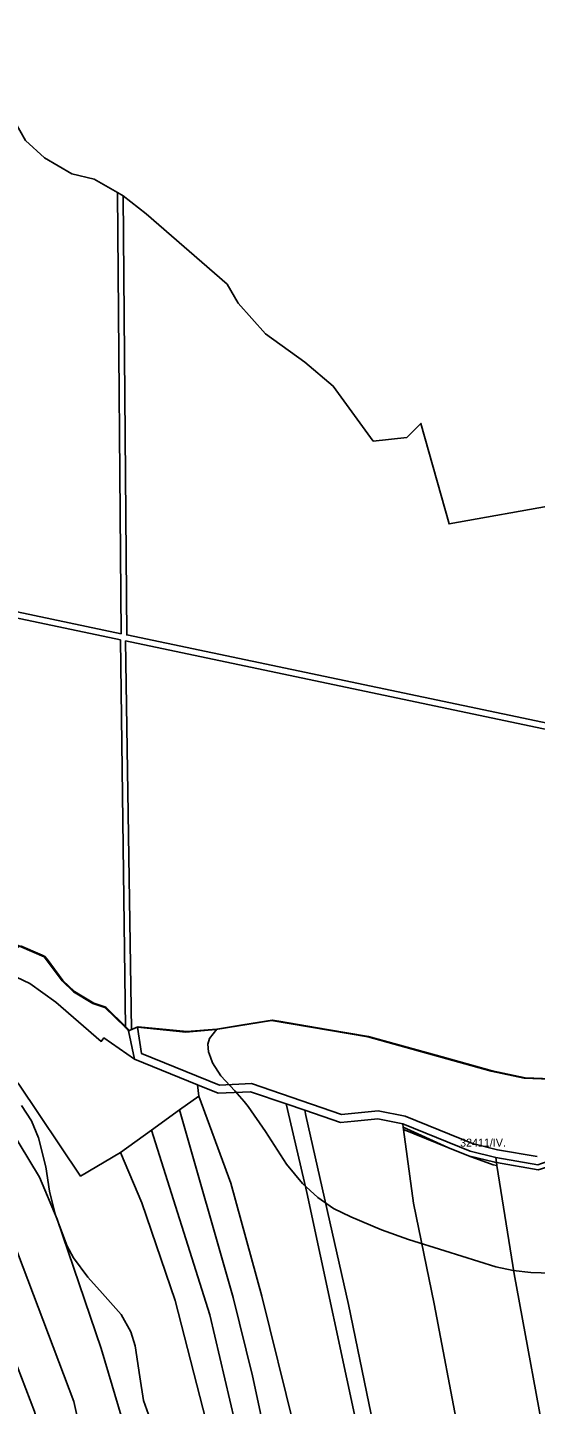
# Model space of a CAD drawing. Extents: x -535894 to -532834, y -1165802 to -1163645.
# Drawn here: x -534487 to -534170, y -1164507 to -1163647 of the extents above; entities that cross this region are included whole.
import ezdxf

# ---------------------------------------------------------------- set-up
doc = ezdxf.new("R2010")
doc.units = 0
for name, color, linetype in [('95560013', 7, 'Continuous'), ('95610013', 7, 'Continuous'), ('95620013', 7, 'Continuous'), ('95630013', 7, 'Continuous'), ('95640013', 7, 'Continuous'), ('95660013', 7, 'Continuous')]:
    doc.layers.add(name, color=color, linetype=linetype)

msp = doc.modelspace()

# ---------------------------------------------------------------- linework, layer by layer
at = {"layer": '95560013'}
for points in [[(-534485.85, -1164244.28), (-534469.68, -1164256.06), (-534441.39, -1164280.53), (-534439.7, -1164278.38), (-534420.68, -1164291.71), (-534381.33, -1164307.72), (-534380.51, -1164314.71), (-534392.48, -1164323.34), (-534409.97, -1164335.95), (-534429.42, -1164349.98), (-534454.21, -1164364.71), (-534492.77, -1164307.32), (-534515.72, -1164281.44), (-534526.13, -1164274.97), (-534521.16, -1164256.66), (-534507.27, -1164234.42)], [(-534526.13, -1164274.97), (-534515.72, -1164281.44), (-534492.77, -1164307.32), (-534454.21, -1164364.71), (-534429.42, -1164349.98), (-534416.02, -1164381.41), (-534395.29, -1164442.42), (-534374.06, -1164525.31), (-534335.46, -1164704.47), (-534321.03, -1164764.37), (-534369.38, -1164771.26), (-534395.1, -1164665.47), (-534403.85, -1164623.02), (-534425.95, -1164524.31), (-534441.36, -1164472.55), (-534468.86, -1164391.61), (-534480, -1164365.41), (-534516.93, -1164304.39), (-534530.72, -1164286.68)], [(-534532.67, -1164291.64), (-534530.72, -1164286.68), (-534516.93, -1164304.39), (-534480, -1164365.41), (-534468.86, -1164391.61), (-534441.36, -1164472.55), (-534425.95, -1164524.31), (-534403.85, -1164623.02), (-534395.1, -1164665.47), (-534369.38, -1164771.26), (-534394.4, -1164775.14), (-534435.14, -1164602.44), (-534447.18, -1164556.51), (-534458.51, -1164505.61), (-534503.01, -1164387.73), (-534528.59, -1164340.68), (-534546.29, -1164312.84), (-534540.94, -1164306.3)], [(-534368.45, -1164312.96), (-534348.23, -1164312.01), (-534325.91, -1164319.65), (-534325.1, -1164323.12), (-534312.95, -1164375.07), (-534279.41, -1164531.26), (-534235.38, -1164737.53), (-534263.41, -1164744.88), (-534259.95, -1164758.7), (-534270.37, -1164759.39), (-534289.39, -1164676.29), (-534296.14, -1164651.27), (-534310.82, -1164581.32), (-534320.94, -1164521.53), (-534341.14, -1164439.8), (-534360.37, -1164369.24), (-534380.51, -1164314.71), (-534381.33, -1164307.72)], [(-534552.41, -1164320.35), (-534546.29, -1164312.84), (-534528.59, -1164340.68), (-534503.01, -1164387.73), (-534458.51, -1164505.61), (-534447.18, -1164556.51), (-534435.14, -1164602.44), (-534394.4, -1164775.14), (-534417.97, -1164782.81), (-534422.37, -1164761.45), (-534445.23, -1164674.2), (-534452.73, -1164639.92), (-534475.43, -1164538.49), (-534482.99, -1164511.95), (-534496.61, -1164476.36), (-534524.39, -1164413.79), (-534547.27, -1164366.74), (-534567.13, -1164333.28)], [(-534380.51, -1164314.71), (-534360.37, -1164369.24), (-534341.14, -1164439.8), (-534320.94, -1164521.53), (-534310.82, -1164581.32), (-534296.14, -1164651.27), (-534289.39, -1164676.29), (-534270.37, -1164759.39), (-534285.75, -1164760.67), (-534304.35, -1164689.65), (-534328.76, -1164574.02), (-534346.86, -1164489.52), (-534358.97, -1164440.63), (-534392.48, -1164323.34)], [(-534392.48, -1164323.34), (-534358.97, -1164440.63), (-534346.86, -1164489.52), (-534328.76, -1164574.02), (-534304.35, -1164689.65), (-534285.75, -1164760.67), (-534302.74, -1164761.94), (-534316.61, -1164710.6), (-534338.42, -1164610.08), (-534358.04, -1164518.08), (-534373.64, -1164451.39), (-534409.97, -1164335.95)], [(-534325.91, -1164319.65), (-534314.28, -1164323.62), (-534313.54, -1164326.89), (-534286.98, -1164445.09), (-534267.22, -1164541.07), (-534255.41, -1164592.77), (-534227.83, -1164735.54), (-534235.38, -1164737.53), (-534279.41, -1164531.26), (-534312.95, -1164375.07), (-534325.1, -1164323.12)], [(-534314.28, -1164323.62), (-534291.92, -1164331.27), (-534283.19, -1164330.42), (-534268.67, -1164329.01), (-534253.1, -1164332.11), (-534252.81, -1164334.22), (-534252.63, -1164335.54), (-534246.42, -1164381.6), (-534233.53, -1164444.63), (-534218.39, -1164524.52), (-534206.45, -1164583.63), (-534189.15, -1164673.8), (-534171.37, -1164752.69), (-534179.77, -1164756.72), (-534195.92, -1164761.38), (-534216.66, -1164764.58), (-534218.72, -1164756.66), (-534224.44, -1164734.65), (-534227.83, -1164735.54), (-534255.41, -1164592.77), (-534267.22, -1164541.07), (-534286.98, -1164445.09), (-534313.54, -1164326.89)], [(-534578.03, -1164342.06), (-534567.13, -1164333.28), (-534547.27, -1164366.74), (-534524.39, -1164413.79), (-534496.61, -1164476.36), (-534482.99, -1164511.95), (-534475.43, -1164538.49), (-534452.73, -1164639.92), (-534445.23, -1164674.2), (-534422.37, -1164761.45), (-534417.97, -1164782.81), (-534464.01, -1164796.91), (-534483.14, -1164727.26), (-534507.98, -1164622.35), (-534527.6, -1164554.86), (-534532.98, -1164540.25), (-534563.85, -1164466.68), (-534596.51, -1164398.57), (-534611.82, -1164369.29), (-534589.62, -1164351.4)], [(-534409.97, -1164335.95), (-534373.64, -1164451.39), (-534358.04, -1164518.08), (-534338.42, -1164610.08), (-534316.61, -1164710.6), (-534302.74, -1164761.94), (-534321.03, -1164764.37), (-534335.46, -1164704.47), (-534374.06, -1164525.31), (-534395.29, -1164442.42), (-534416.02, -1164381.41), (-534429.42, -1164349.98)], [(-534252.63, -1164335.54), (-534225.01, -1164346.8), (-534212.04, -1164352.1), (-534196.56, -1164357.78), (-534194.29, -1164358.08), (-534183.63, -1164425.89), (-534161.35, -1164546.99), (-534154.51, -1164595.51), (-534134.42, -1164692.7), (-534129.11, -1164725.09), (-534140.42, -1164734.83), (-534159.42, -1164746.94), (-534171.37, -1164752.69), (-534189.15, -1164673.8), (-534206.45, -1164583.63), (-534218.39, -1164524.52), (-534233.53, -1164444.63), (-534246.42, -1164381.6)], [(-534212.04, -1164352.1), (-534195.66, -1164356.15), (-534194.56, -1164356.33), (-534194.29, -1164358.08), (-534196.56, -1164357.78)], [(-534143.2, -1164352.52), (-534139.1, -1164352.62), (-534137.95, -1164353.25), (-534137.54, -1164357.79), (-534134.7, -1164388.64), (-534128.98, -1164436.89), (-534104.44, -1164574.12), (-534091.65, -1164672.4), (-534102.21, -1164694.14), (-534107.73, -1164701.96), (-534116.22, -1164713.99), (-534129.11, -1164725.09), (-534134.42, -1164692.7), (-534154.51, -1164595.51), (-534161.35, -1164546.99), (-534183.63, -1164425.89), (-534194.29, -1164358.08), (-534194.56, -1164356.33), (-534168.47, -1164360.79), (-534166.4, -1164360.11)]]:
    msp.add_lwpolyline(points, close=True, dxfattribs=at)
msp.add_lwpolyline([(-534169.08, -1164352.57), (-534194.02, -1164348.32), (-534209.55, -1164344.47), (-534251.65, -1164327.3), (-534268.42, -1164323.97), (-534291.32, -1164326.19), (-534347.51, -1164306.97), (-534367.58, -1164307.92), (-534416.31, -1164288.09), (-534418.8, -1164271.7), (-534388.51, -1164274.7), (-534369.81, -1164273.2), (-534335.13, -1164267.45), (-534274.99, -1164277.69), (-534197.87, -1164299.21), (-534177.29, -1164303.6), (-534144.82, -1164304.74)], dxfattribs=at)
at = {"layer": '95610013'}
msp.add_lwpolyline([(-534492.39, -1164221.02), (-534477.05, -1164227.75), (-534465.85, -1164242.8), (-534458.72, -1164249.64), (-534446.52, -1164256.91), (-534439.05, -1164259.47), (-534426.3, -1164271.96), (-534424.3, -1164273.92), (-534420.68, -1164291.71), (-534439.7, -1164278.38), (-534441.39, -1164280.53), (-534469.68, -1164256.06), (-534485.85, -1164244.28), (-534507.27, -1164234.42), (-534503.09, -1164227.73)], close=True, dxfattribs=at)
at = {"layer": '95620013'}
for points in [[(-534579.5, -1163650.15), (-534570.98, -1163646.93), (-534514.86, -1163686.14), (-534495.67, -1163705.05), (-534488.62, -1163717.48), (-534476.78, -1163728.4), (-534459.7, -1163738.33), (-534445.87, -1163741.61), (-534431.31, -1163750.05), (-534428.93, -1164025.8), (-534576.69, -1163994.7), (-534580.33, -1163993.93), (-534735.68, -1163961.24), (-534749.05, -1163747.99), (-534718.97, -1163730.71), (-534642.84, -1163687.62), (-534599.15, -1163661.49), (-534591.03, -1163654.51), (-534583.72, -1163651.75)], [(-534427.72, -1163752.13), (-534413.24, -1163763.36), (-534362.72, -1163807.37), (-534355.93, -1163819.24), (-534338.84, -1163838.27), (-534314.16, -1163855.97), (-534296.47, -1163870.97), (-534271.49, -1163905.38), (-534250.57, -1163903.14), (-534241.76, -1163894.34), (-534224.22, -1163957.18), (-534156.41, -1163945.04), (-534157.94, -1163978.43), (-534146.05, -1164041.92), (-534145.18, -1164064.32), (-534137.15, -1164087.2), (-534425.41, -1164026.54)], [(-534735.42, -1163965.07), (-534580.94, -1163997.64), (-534577.82, -1163998.3), (-534429.37, -1164029.61), (-534426.3, -1164271.96), (-534439.05, -1164259.47), (-534446.52, -1164256.91), (-534458.72, -1164249.64), (-534465.85, -1164242.8), (-534477.05, -1164227.75), (-534492.39, -1164221.02), (-534521.68, -1164205.56), (-534554.26, -1164192.45), (-534591.23, -1164182.82), (-534594.62, -1164181.93), (-534604.82, -1164180.29), (-534627.51, -1164173.48), (-534643.92, -1164165.11), (-534663.32, -1164170.6), (-534682.2, -1164171.34), (-534689.58, -1164178.65), (-534705.88, -1164181.51), (-534719.55, -1164186.71)], [(-534426.2, -1164030.27), (-534134.69, -1164091.75), (-534131.77, -1164097.12), (-534123.86, -1164105.89), (-534115.56, -1164113.93), (-534097.11, -1164148.68), (-534086.47, -1164183.86), (-534079.09, -1164221.21), (-534079.7, -1164259.55), (-534075.33, -1164283.15), (-534074.04, -1164285.93), (-534144.82, -1164304.74), (-534177.29, -1164303.6), (-534197.87, -1164299.21), (-534274.99, -1164277.69), (-534335.13, -1164267.45), (-534369.81, -1164273.2), (-534388.51, -1164274.7), (-534418.8, -1164271.7), (-534422.39, -1164273.15)]]:
    msp.add_lwpolyline(points, close=True, dxfattribs=at)
msp.add_lwpolyline([(-534576.69, -1163994.7), (-534428.93, -1164025.8), (-534431.31, -1163750.05), (-534427.72, -1163752.13), (-534425.41, -1164026.54), (-534137.15, -1164087.2), (-534134.69, -1164091.75), (-534426.2, -1164030.27), (-534422.39, -1164273.15), (-534424.3, -1164273.92), (-534426.3, -1164271.96), (-534429.37, -1164029.61), (-534577.82, -1163998.3)], dxfattribs=at)
at = {"layer": '95630013'}
msp.add_lwpolyline([(-534168.7, -1164357.7), (-534195.05, -1164353.21), (-534211.11, -1164349.23), (-534253.1, -1164332.11), (-534268.67, -1164329.01), (-534283.19, -1164330.42), (-534291.92, -1164331.27), (-534314.28, -1164323.62), (-534325.91, -1164319.65), (-534348.23, -1164312.01), (-534368.45, -1164312.96), (-534381.33, -1164307.72), (-534420.68, -1164291.71), (-534424.3, -1164273.92), (-534422.39, -1164273.15), (-534418.8, -1164271.7), (-534416.31, -1164288.09), (-534367.58, -1164307.92), (-534347.51, -1164306.97), (-534291.32, -1164326.19), (-534268.42, -1164323.97), (-534251.65, -1164327.3), (-534209.55, -1164344.47), (-534194.02, -1164348.32), (-534169.08, -1164352.57)], dxfattribs=at)
at = {"layer": '95640013'}
for points in [[(-534253.1, -1164332.11), (-534211.11, -1164349.23), (-534195.05, -1164353.21), (-534194.56, -1164356.33), (-534195.66, -1164356.15), (-534212.04, -1164352.1), (-534225.01, -1164346.8), (-534252.81, -1164334.22)], [(-534252.81, -1164334.22), (-534225.01, -1164346.8), (-534252.63, -1164335.54)], [(-534143.64, -1164349.5), (-534138.28, -1164349.65), (-534137.95, -1164353.25), (-534139.1, -1164352.62), (-534143.2, -1164352.52), (-534166.4, -1164360.11), (-534168.47, -1164360.79), (-534194.56, -1164356.33), (-534195.05, -1164353.21), (-534168.7, -1164357.7), (-534166.42, -1164356.96)]]:
    msp.add_lwpolyline(points, close=True, dxfattribs=at)
at = {"layer": '95660013'}
for points in [[(-534488.62, -1163717.48), (-534476.78, -1163728.4), (-534459.7, -1163738.33), (-534445.87, -1163741.61), (-534431.31, -1163750.05), (-534427.72, -1163752.13), (-534413.24, -1163763.36), (-534362.72, -1163807.37), (-534355.93, -1163819.24), (-534338.84, -1163838.27), (-534314.16, -1163855.97), (-534296.47, -1163870.97), (-534271.49, -1163905.38), (-534250.57, -1163903.14), (-534241.76, -1163894.34), (-534224.22, -1163957.18), (-534156.41, -1163945.04)], [(-534491.819, -1164220.783), (-534478.19, -1164226.769), (-534476.481, -1164227.52), (-534475.221, -1164229.212), (-534465.277, -1164242.57), (-534458.149, -1164249.409), (-534454.274, -1164251.719), (-534445.949, -1164256.682), (-534438.476, -1164259.234), (-534425.73, -1164271.728), (-534423.725, -1164273.692), (-534421.818, -1164272.918), (-534419.463, -1164271.967), (-534418.226, -1164271.467), (-534396.408, -1164273.634), (-534387.935, -1164274.475), (-534369.237, -1164272.974), (-534373.79, -1164278.75), (-534374.741, -1164282.33), (-534374.421, -1164287.19), (-534373.226, -1164290.41), (-534371.88, -1164294.04), (-534366.78, -1164302.16), (-534357.86, -1164311.4), (-534352.209, -1164318.231), (-534349.674, -1164321.296), (-534338.75, -1164336.8), (-534325.69, -1164357.35), (-534315.73, -1164369.379), (-534306.17, -1164378.14), (-534296.3, -1164384.91), (-534285.547, -1164390.167), (-534266.349, -1164398.29), (-534249.55, -1164404.341), (-534226.85, -1164411.43), (-534195.051, -1164421.361), (-534184.25, -1164423.85), (-534173.231, -1164425.044), (-534160.19, -1164425.52)], [(-534144.242, -1164304.527), (-534176.712, -1164303.379), (-534197.303, -1164298.995), (-534228.418, -1164290.309), (-534274.419, -1164277.467), (-534300.363, -1164273.048), (-534330.488, -1164267.917), (-534334.561, -1164267.224), (-534353.038, -1164270.288), (-534369.237, -1164272.974), (-534387.935, -1164274.475), (-534396.408, -1164273.634), (-534418.226, -1164271.467), (-534419.463, -1164271.967), (-534421.818, -1164272.918), (-534423.725, -1164273.692), (-534425.73, -1164271.728), (-534438.476, -1164259.234), (-534445.949, -1164256.682), (-534454.274, -1164251.719), (-534458.149, -1164249.409), (-534465.277, -1164242.57), (-534475.221, -1164229.212), (-534476.481, -1164227.52), (-534478.19, -1164226.769), (-534491.819, -1164220.783)], [(-534160.19, -1164425.52), (-534173.231, -1164425.044), (-534184.25, -1164423.85), (-534195.051, -1164421.361), (-534226.85, -1164411.43), (-534249.55, -1164404.341), (-534266.349, -1164398.29), (-534285.547, -1164390.167), (-534296.3, -1164384.91), (-534306.17, -1164378.14), (-534315.73, -1164369.379), (-534325.69, -1164357.35), (-534338.75, -1164336.8), (-534349.674, -1164321.296), (-534352.209, -1164318.231), (-534357.86, -1164311.4), (-534366.78, -1164302.16), (-534371.88, -1164294.04), (-534373.226, -1164290.41), (-534374.421, -1164287.19), (-534374.741, -1164282.33), (-534373.79, -1164278.75), (-534369.237, -1164272.974), (-534353.038, -1164270.288), (-534334.561, -1164267.224), (-534330.488, -1164267.917), (-534300.363, -1164273.048), (-534274.419, -1164277.467), (-534228.418, -1164290.309), (-534197.303, -1164298.995), (-534176.712, -1164303.379), (-534144.242, -1164304.527)], [(-534411.86, -1164513.84), (-534415.04, -1164505.08), (-534417.27, -1164490.19), (-534420.167, -1164470.849), (-534422.93, -1164462), (-534428.82, -1164451.25), (-534440.53, -1164438.19), (-534449.654, -1164428.014), (-534458.68, -1164415.89), (-534462.59, -1164408.48), (-534470.15, -1164388.57), (-534473.58, -1164374.24), (-534475.89, -1164358.86), (-534480.5, -1164340.79), (-534484.96, -1164330.27), (-534491.235, -1164320.721)], [(-534491.235, -1164320.721), (-534484.96, -1164330.27), (-534480.5, -1164340.79), (-534475.89, -1164358.86), (-534473.58, -1164374.24), (-534470.15, -1164388.57), (-534462.59, -1164408.48), (-534458.68, -1164415.89), (-534449.654, -1164428.014), (-534440.53, -1164438.19), (-534428.82, -1164451.25), (-534422.93, -1164462), (-534420.167, -1164470.849), (-534417.27, -1164490.19), (-534415.04, -1164505.08), (-534411.86, -1164513.84)]]:
    msp.add_lwpolyline(points, dxfattribs=at)

# ---------------------------------------------------------------- texts
msp.add_text('32411/IV.', height=5, rotation=0, dxfattribs=at).set_placement((-534217.314, -1164346.372))

doc.saveas('drawing.dxf')
